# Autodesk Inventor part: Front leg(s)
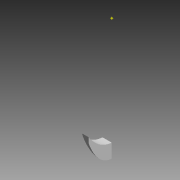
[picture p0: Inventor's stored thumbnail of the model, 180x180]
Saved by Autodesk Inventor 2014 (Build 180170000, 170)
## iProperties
Created: 2013-09
Part Number: Front leg(s)
Material: Generic
Document SubType Name: Modeling
Designer: Joey Mason
Appearance: Reflective - White
Mass: 1001.7 g
Surface Area: 2819.14 cm^2
Volume: 1001.7 cm^3
Density: 1 g/cm^3
Author: Joey Mason
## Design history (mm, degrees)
sketch "Sketch1"
  geometry: L1 (-1045.953, 551.745)-(799.079, 551.745); L2 (799.079, 551.745)-(799.079, -678.891); L3 (799.079, -678.891)-(-1045.953, -678.891); L4 (-1045.953, -678.891)-(-1045.953, 551.745); 4 further points; 1 other entity
  constraints: 1 vertical, 6 other
  node "Image1"
sketch "Sketch6"
  geometry: 5 further points; 1 other entity
  constraints: 1 coincident, 4 other
sketch "Sketch7"
  geometry: 4 further points; 1 other entity
  constraints: 1 coincident, 4 other
sketch "Sketch8"
  geometry: 4 further points; 1 other entity
  constraints: 4 other
sketch "Sketch9"
  geometry: 5 further points; 1 other entity
  constraints: 1 coincident, 2 other
workpoint "Work Point5"
loft "Loft2" dims "d70" = 0, "d71" = 90 deg, "d72" = 0, "d73" = 90 deg, "d74" = 0, "d75" = 90 deg, "d76" = 0, "d77" = 90 deg, "d78" = 0, "d79" = 90 deg, "d80" = 0, "d81" = 90 deg, "d82" = 0, "d83" = 90 deg
workplane "Work Plane1"
sketch "Sketch10"
  geometry: L1 (0, 0)-(0.002, -165.1); L2 (-72.009, 197.105)-(-42.932, 117.215); L3 (-29.628, -144.286)-(-47.688, -246.71); L4 (-47.688, -246.71)-(-267.69, 18.133); L5 (-267.69, 18.133)-(-72.009, 197.105); L6 (267.69, 18.139)-(72.005, 197.107); L7 (72.005, 197.107)-(42.929, 117.216); L8 (47.694, -246.709)-(267.69, 18.139); L9 (29.631, -144.286)-(47.694, -246.709); L10 (-72.009, 197.105)-(-78.879, 319.237); L11 (-78.879, 319.237)-(96.407, 329.096); L12 (96.407, 329.096)-(72.977, 196.217); L13 (29.631, -144.286)-(47.694, -246.709); 4 further points; 3 other entities
  constraints: 26 end point, 5 symmetric about line, 3 coincident, 1 collinear, 1 parallel, 1 perpendicular, 1 point on line, 16 other
extrude "Extrusion5" cut sketch "Sketch10" distance "d111" = 279.4; taper "d112" = 0 deg
sketch "Sketch14"
  geometry: L1 (0, 0)-(-369.02, 0); L2 (-369.02, 0)-(-369.02, -183.383); L3 (-369.02, -183.383)-(0, -183.383); L4 (0, -183.383)-(0, 0)
  constraints: 8 end point, 2 parallel, 1 horizontal, 1 perpendicular
extrude "Extrusion6" cut sketch "Sketch14" stored distance "d113" = 279.4; taper "d114" = 0 deg
workplane "Work Plane2"
workplane "Work Plane3"
sketch "Sketch16"
  geometry: L1 (48.491, 34.064)-(0, 0); 2 further points; 1 other entity
  constraints: 2 end point, 2 other
extrude "Extrusion7" join sketch "Sketch16" distance "d115" = 127; taper "d116" = 0 deg
sketch "Sketch17"
  geometry: L1 (-165.1, 106.554)-(-173.055, 130.917); L2 (-173.055, 130.917)-(-134.733, 130.917); L3 (-134.733, 130.917)-(-144.286, 106.104); L4 (-165.1, 106.554)-(-144.286, 106.104); 1 further point
  constraints: 8 end point, 1 horizontal, 1 other
extrude "Extrusion8" cut sketch "Sketch17" stored distance "d117" = 127; taper "d118" = 0 deg
sketch "Sketch18"
  geometry: L1 (0, 0)-(59.259, 0) reference; L2 (59.259, 0)-(59.259, 106.104) reference; L3 (0, 106.104)-(59.259, 106.104) reference; L4 (0, 0)-(0, 106.104) reference; 1 further point
extrude "Extrusion9" join sketch "Sketch18" distance "d119" = 5.08; taper "d120" = 0 deg
sketch "Sketch19"
  geometry: L1 (106.104, -103.998)-(106.104, 0) reference; L2 (0, 0)-(106.104, 0) reference; L3 (0, 0)-(-4.488, 9.849); 1 further point
  constraints: 2 end point, 1 other
sketch "Sketch20"
  geometry: L1 (29.631, -144.286)-(27.921, -134.587) reference; L2 (28.502, -137.88)-(32.223, -137.555); L3 (32.223, -137.555)-(29.631, -144.286); 1 further point
  constraints: 4 end point, 1 point on line
extrude "Extrusion10" cut sketch "Sketch20" distance "d121" = 279.4; taper "d122" = 0 deg
sketch "Sketch21"
  geometry: L1 (106.104, -0.003)-(106.104, 0) reference; L2 (106.104, 0)-(0, 0) reference; L3 (0, 0)-(0, -104.004) reference; L4 (106.104, 0)-(112.153, 12.957); 1 further point
  constraints: 2 end point, 1 other
sketch "Sketch22"
  geometry: L1 (-29.628, -144.286)-(-27.378, -131.526) reference; L2 (-29.628, -144.286)-(-36.3, -132.786); L3 (-36.3, -132.786)-(-27.378, -131.526); 1 further point
  constraints: 4 end point
extrude "Extrusion11" cut sketch "Sketch22" distance "d123" = 279.4; taper "d124" = 0 deg
sketch "Sketch23"
  geometry: L1 (-165.1, 106.554)-(-134.627, 105.895); L2 (-134.627, 105.895)-(-135.664, 107.432); L3 (-135.664, 107.432)-(-165.1, 106.554); 2 further points
  constraints: 6 end point, 1 other
  dimensions: "d125" = 30.48 distance of L1.start L1.end
extrude "Extrusion12" cut sketch "Sketch23" stored distance "d126" = 279.4; taper "d127" = 0 deg
sketch "Sketch24"
  geometry: L1 (-139.206, 105.994)-(-139.206, 0) reference; L2 (-139.206, 105.994)-(-141.746, 105.994); L3 (-139.206, 105.994)-(-141.746, 105.994); L4 (-141.746, 105.994)-(-141.746, -3.05); L5 (-141.746, -3.05)-(-139.206, -3.05); L6 (-139.206, -3.05)-(-139.206, 105.994); L7 (-141.746, 105.994)-(-141.746, 117.821); L8 (-141.746, 117.821)-(-139.206, 105.994); 1 further point
  constraints: 14 end point, 3 parallel, 2 perpendicular, 1 horizontal
  dimensions: "d128" = 2.54 distance of L1.start L2.end
extrude "Extrusion13" cut sketch "Sketch24" stored distance "d129" = 279.4; taper "d130" = 0 deg
sketch "Sketch25"
  geometry: L1 (-141.746, 0)-(-141.746, 106.049) reference; L2 (-246.704, 0)-(-141.746, 0) reference; L3 (-246.704, 0)-(-216.224, 0); L4 (-246.704, 0)-(-223.844, 0); 2 further points
  constraints: 4 end point, 2 point on line, 3 other
  dimensions: "d131" = 30.48 distance of L2.start L3.end; "d134" = 22.86 distance of L2.start L4.end
extrude "Extrusion15" cut sketch "Sketch25" stored distance "d135" = 279.4; taper "d136" = 0 deg
sketch "Sketch26"
  geometry: L1 (0, 0)-(292.813, 0); L2 (292.813, 0)-(292.813, -376.635); L3 (292.813, -376.635)-(0, -376.635); L4 (0, -376.635)-(0, 0)
  constraints: 8 end point, 2 parallel, 1 horizontal, 1 perpendicular
extrude "Extrusion16" cut sketch "Sketch26" stored distance "d137" = 279.4; taper "d138" = 0 deg
body "Solid2"
other parameters: "d85" = 132.08
